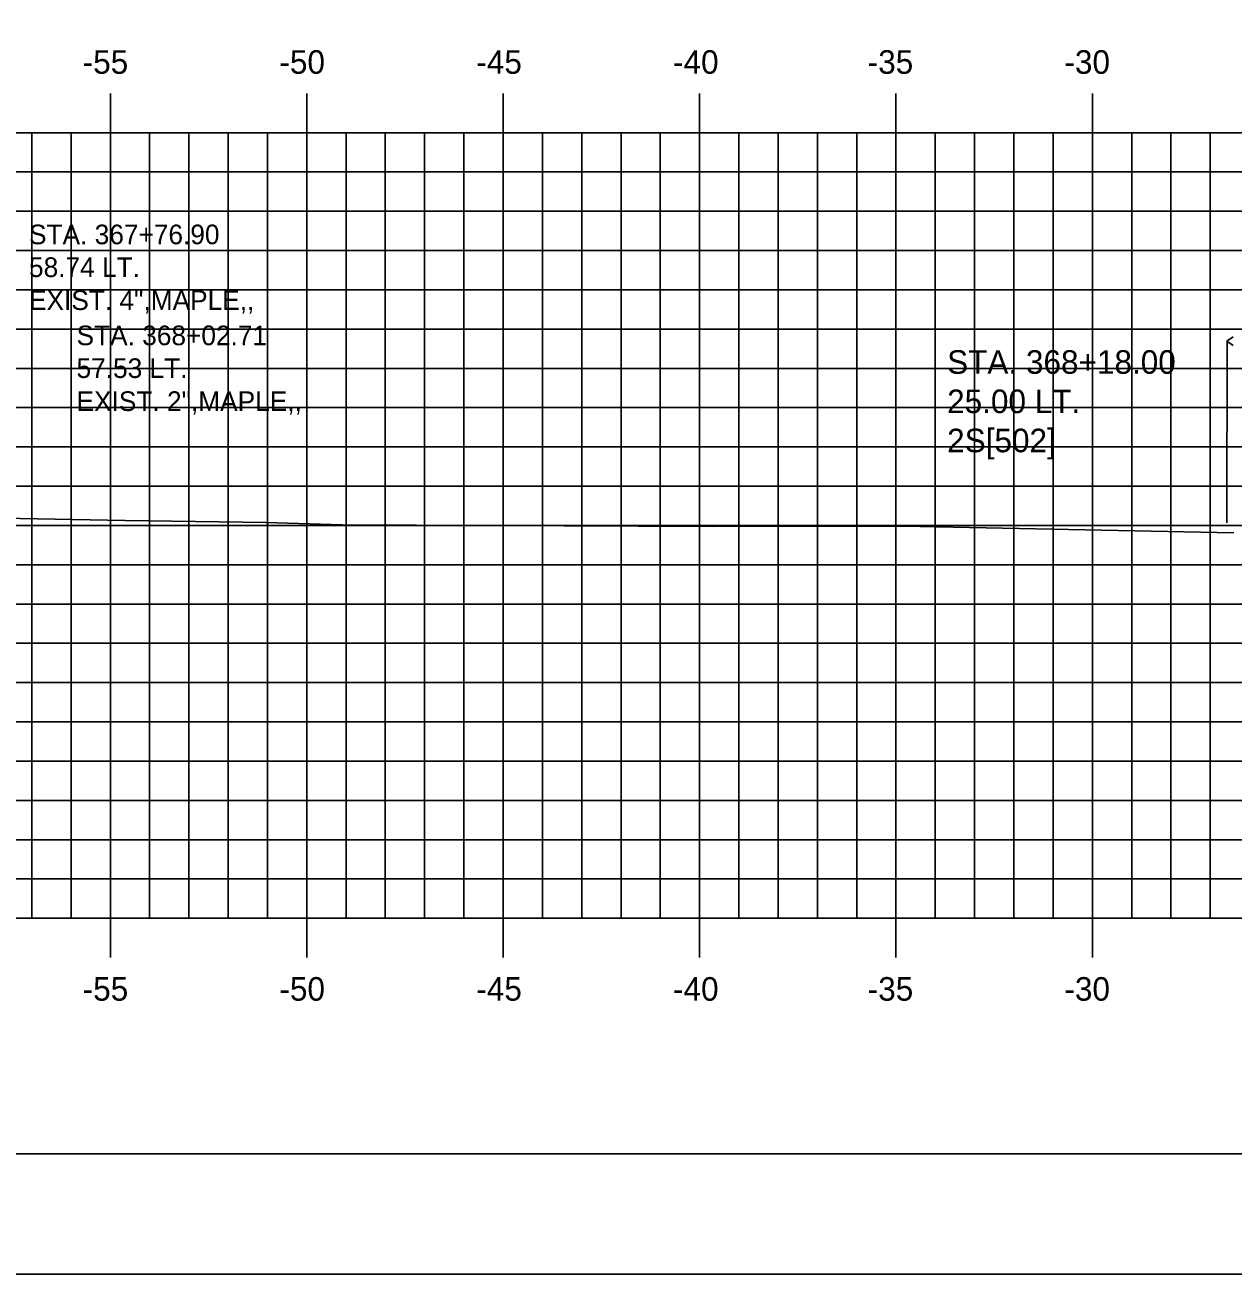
# Model space of a CAD drawing. Extents: x 1147855 to 1148025, y 608981 to 609091.
# Drawn here: x 1147881.04 to 1147911.79, y 608981.28 to 609013.08 of the extents above; entities that cross this region are included whole.
import ezdxf

# ---------------------------------------------------------------- set-up
doc = ezdxf.new("R2010")
doc.units = 0
for name, color, linetype in [('BORDER', 7, 'Continuous'), ('D_Text_Monospaced', 7, 'Continuous'), ('D_Text_Standard', 7, 'Continuous'), ('H_V ANNOTATION', 7, 'Continuous'), ('MAJOR', 7, 'Continuous'), ('MINOR', 7, 'Continuous'), ('PLOT BOUNDARY', 7, 'Continuous'), ('S_Roadway_Centerline', 7, 'Continuous'), ('S_Utilities_Pole_Power', 7, 'Continuous')]:
    doc.layers.add(name, color=color, linetype=linetype)

msp = doc.modelspace()

# ---------------------------------------------------------------- linework, layer by layer
at = {"layer": 'BORDER'}
msp.add_lwpolyline([(1147863.211, 608984.335), (1148023.211, 608984.335), (1148023.211, 609089.335), (1147863.211, 609089.335)], close=True, dxfattribs=at)
at = {"layer": 'MAJOR'}
for p, q in [((1147883.211, 609011.337), (1147883.211, 609010.335)), ((1147888.211, 609011.337), (1147888.211, 609010.335)), ((1147893.211, 609011.337), (1147893.211, 609010.335)), ((1147898.211, 609011.337), (1147898.211, 609010.335)), ((1147903.211, 609011.337), (1147903.211, 609010.335)), ((1147908.211, 609011.337), (1147908.211, 609010.335)), ((1147868.211, 609010.335), (1148008.211, 609010.335)), ((1147868.211, 609010.335), (1148008.211, 609010.335)), ((1147883.211, 608990.335), (1147883.211, 609010.335)), ((1147888.211, 608990.335), (1147888.211, 609010.335)), ((1147893.211, 608990.335), (1147893.211, 609010.335)), ((1147898.211, 608990.335), (1147898.211, 609010.335)), ((1147903.211, 608990.335), (1147903.211, 609010.335)), ((1147908.211, 608990.335), (1147908.211, 609010.335)), ((1147868.211, 609005.335), (1148008.211, 609005.335)), ((1147868.211, 609000.335), (1148008.211, 609000.335)), ((1147868.211, 608995.335), (1148008.211, 608995.335)), ((1147868.211, 608990.335), (1148008.211, 608990.335)), ((1147868.211, 608990.335), (1148008.211, 608990.335)), ((1147883.211, 608989.333), (1147883.211, 608990.335)), ((1147888.211, 608989.333), (1147888.211, 608990.335)), ((1147893.211, 608989.333), (1147893.211, 608990.335)), ((1147898.211, 608989.333), (1147898.211, 608990.335)), ((1147903.211, 608989.333), (1147903.211, 608990.335)), ((1147908.211, 608989.333), (1147908.211, 608990.335))]:
    msp.add_line(p, q, dxfattribs=at)
at = {"layer": 'MINOR'}
for p, q in [((1147881.211, 608990.335), (1147881.211, 609010.335)), ((1147882.211, 608990.335), (1147882.211, 609010.335)), ((1147884.211, 608990.335), (1147884.211, 609010.335)), ((1147885.211, 608990.335), (1147885.211, 609010.335)), ((1147886.211, 608990.335), (1147886.211, 609010.335)), ((1147887.211, 608990.335), (1147887.211, 609010.335)), ((1147889.211, 608990.335), (1147889.211, 609010.335)), ((1147890.211, 608990.335), (1147890.211, 609010.335)), ((1147891.211, 608990.335), (1147891.211, 609010.335)), ((1147892.211, 608990.335), (1147892.211, 609010.335)), ((1147894.211, 608990.335), (1147894.211, 609010.335)), ((1147895.211, 608990.335), (1147895.211, 609010.335)), ((1147896.211, 608990.335), (1147896.211, 609010.335)), ((1147897.211, 608990.335), (1147897.211, 609010.335)), ((1147899.211, 608990.335), (1147899.211, 609010.335)), ((1147900.211, 608990.335), (1147900.211, 609010.335)), ((1147901.211, 608990.335), (1147901.211, 609010.335)), ((1147902.211, 608990.335), (1147902.211, 609010.335)), ((1147904.211, 608990.335), (1147904.211, 609010.335)), ((1147905.211, 608990.335), (1147905.211, 609010.335)), ((1147906.211, 608990.335), (1147906.211, 609010.335)), ((1147907.211, 608990.335), (1147907.211, 609010.335)), ((1147909.211, 608990.335), (1147909.211, 609010.335)), ((1147910.211, 608990.335), (1147910.211, 609010.335)), ((1147911.211, 608990.335), (1147911.211, 609010.335)), ((1147868.211, 609009.335), (1148008.211, 609009.335)), ((1147868.211, 609008.335), (1148008.211, 609008.335)), ((1147868.211, 609007.335), (1148008.211, 609007.335)), ((1147868.211, 609006.335), (1148008.211, 609006.335)), ((1147868.211, 609004.335), (1148008.211, 609004.335)), ((1147868.211, 609003.335), (1148008.211, 609003.335)), ((1147868.211, 609002.335), (1148008.211, 609002.335)), ((1147868.211, 609001.335), (1148008.211, 609001.335)), ((1147868.211, 608999.335), (1148008.211, 608999.335)), ((1147868.211, 608998.335), (1148008.211, 608998.335)), ((1147868.211, 608997.335), (1148008.211, 608997.335)), ((1147868.211, 608996.335), (1148008.211, 608996.335)), ((1147868.211, 608994.335), (1148008.211, 608994.335)), ((1147868.211, 608993.335), (1148008.211, 608993.335)), ((1147868.211, 608992.335), (1148008.211, 608992.335)), ((1147868.211, 608991.335), (1148008.211, 608991.335))]:
    msp.add_line(p, q, dxfattribs=at)
at = {"layer": 'PLOT BOUNDARY'}
msp.add_lwpolyline([(1147855.117, 608981.276), (1148025.117, 608981.276), (1148025.117, 609091.276), (1147855.117, 609091.276)], close=True, dxfattribs=at)
at = {"layer": 'S_Roadway_Centerline'}
msp.add_lwpolyline([(1147873.309, 609000.656), (1147883.585, 609000.465), (1147887.165, 609000.407), (1147889.112, 609000.348), (1147898.528, 609000.308), (1147903.402, 609000.314), (1147911.816, 609000.149)], dxfattribs=at)
at = {"layer": 'S_Utilities_Pole_Power'}
for p, q in [((1147911.635, 609005.024), (1147911.791, 609005.135)), ((1147911.635, 609000.405), (1147911.638, 609005.024)), ((1147911.791, 609004.913), (1147911.635, 609005.024))]:
    msp.add_line(p, q, dxfattribs=at)

# ---------------------------------------------------------------- texts
at = {"layer": 'D_Text_Monospaced'}
for s, height, p in [('STA. 367+76.90', 0.49998, (1147881.14, 609007.495)), ('58.74 LT.', 0.5, (1147881.14, 609006.661)), ('EXIST. 4",MAPLE,,', 0.49998, (1147881.14, 609005.821)), ('STA. 368+02.71', 0.49998, (1147882.35, 609004.924)), ('57.53 LT.', 0.5, (1147882.35, 609004.09)), ('EXIST. 2",MAPLE,,', 0.49998, (1147882.35, 609003.25))]:
    msp.add_text(s, height=height, dxfattribs=at).set_placement(p)
at = {"layer": 'D_Text_Standard'}
for s, p in [('STA. 368+18.00', (1147904.513, 609004.197)), ('25.00 LT.', (1147904.513, 609003.195)), ('2S[502] ', (1147904.513, 609002.199))]:
    msp.add_text(s, height=0.6, dxfattribs=at).set_placement(p)
at = {"layer": 'H_V ANNOTATION'}
for s, p in [('-55', (1147882.507, 609011.835)), ('-50', (1147887.515, 609011.835)), ('-45', (1147892.528, 609011.835)), ('-40', (1147897.536, 609011.835)), ('-35', (1147902.491, 609011.835)), ('-30', (1147907.499, 609011.835)), ('-55', (1147882.507, 608988.235)), ('-50', (1147887.515, 608988.235)), ('-45', (1147892.528, 608988.235)), ('-40', (1147897.536, 608988.235)), ('-35', (1147902.491, 608988.235)), ('-30', (1147907.499, 608988.235))]:
    msp.add_text(s, height=0.6, dxfattribs=at).set_placement(p)

doc.saveas('drawing.dxf')
